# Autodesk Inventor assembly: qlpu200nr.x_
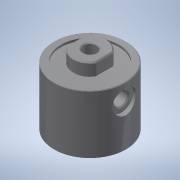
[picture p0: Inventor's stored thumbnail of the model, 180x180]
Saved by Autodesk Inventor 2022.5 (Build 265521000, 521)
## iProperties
Part Number: qlpu200nr.x_
Material: 一般
Document SubType Name: Assembly
Designer: ImaoCorp
Sending System: SOLIDWORKS 2017-2017317
MC: AMD64
MC_MODEL: Intel64 Family 6 Model 60 Stepping 3, GenuineIntel
OS: Windows_NT
FRU: Parasolid Version 29.0, build 201,  4-17-2017
FORMAT: text
GUISE: transmit
KEY: qlpu200nr
FILE: qlpu200nr.x_t
DATE: Wed Sep 04 15:44:19 2019
Author: ImaoCorp
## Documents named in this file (3)
- X:\14_SW2022-Inv2022\00_全2023-1023新製品(TCC)まで\q\qlpu200nr\QLPU200NR.iam
- X:\14_SW2022-Inv2022\00_全2023-1023新製品(TCC)まで\q\qlpu200nr\qlpu200nr_01.ipt
- X:\14_SW2022-Inv2022\00_全2023-1023新製品(TCC)まで\q\qlpu200nr\qlpu200nr_02.ipt
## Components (2 placed, 2 different names)
1. qlpu200nr_01
2. qlpu200nr_02
